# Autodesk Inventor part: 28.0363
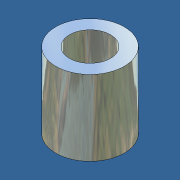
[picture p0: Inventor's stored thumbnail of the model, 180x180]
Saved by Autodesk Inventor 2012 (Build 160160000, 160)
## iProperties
Created: 2011-09
Part Number: 28.0363
Document SubType Name: Modeling
Designer: Administrator
Density: 7.85 g/cm^3
Mass: 3.7523 g
Surface Area: 7.50246 cm^2
Volume: 0.477999 cm^3
Material: Steel
Description: M8 DISTANCE RING
Vendor: S
Author: Administrator
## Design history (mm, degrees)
feature "Base1"
body "Solid1"
